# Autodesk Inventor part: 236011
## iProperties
Created: 2006-08
Part Number: 236011
Material: St vz
Description: Scheibe
Vendor: Autodesk Inc.
Document SubType Name: Modeling
Standard: DIN 125
Designer: I.Baliuc
Standards Organization: DIN
Language: de-DE
Size Designation: A 6.4
Categories: <MemberInstance Version="R10.0.0"><Categories><Category DisplayName="Schrauben" InternalName="e4da775c-781d-43d5-af7c-5136215cf5a6" Mnemonic="FSTN"><Category Di
Density: 7.85 g/cm^3
Mass: 1.01645 g
Surface Area: 2.54343 cm^2
Volume: 0.129484 cm^3
Abmessung: A 6
Author: T.Messerschmitt
Comments: DIN 125 - A 6.4
Revision Number: 236011
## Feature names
1. Körper [Extrusion]
